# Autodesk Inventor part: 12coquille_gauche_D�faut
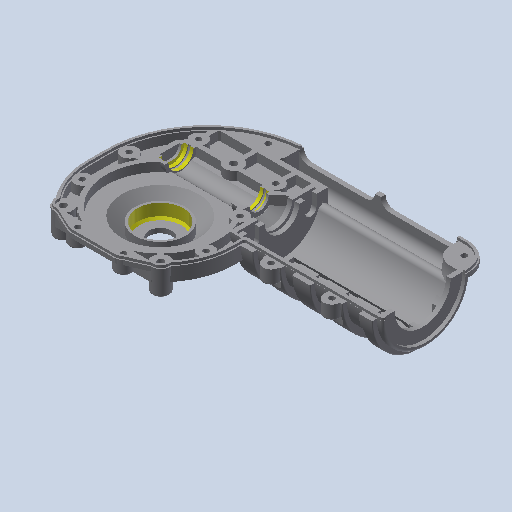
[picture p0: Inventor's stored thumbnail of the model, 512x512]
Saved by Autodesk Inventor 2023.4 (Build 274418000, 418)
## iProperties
Created: 2011-01
Part Number: 12coquille_gauche_D�faut
Document SubType Name: Modeling
Designer: eric
Density: 1 g/cm^3
Mass: 230.232 g
Surface Area: 1193.24 cm^2
Volume: 230.232 cm^3
Material: Générique
Appearance: Par défaut
Author: eric
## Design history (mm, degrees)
feature "Base1"
node "Corps solides"
node "Corps surfaciques"
node "Solide1"
